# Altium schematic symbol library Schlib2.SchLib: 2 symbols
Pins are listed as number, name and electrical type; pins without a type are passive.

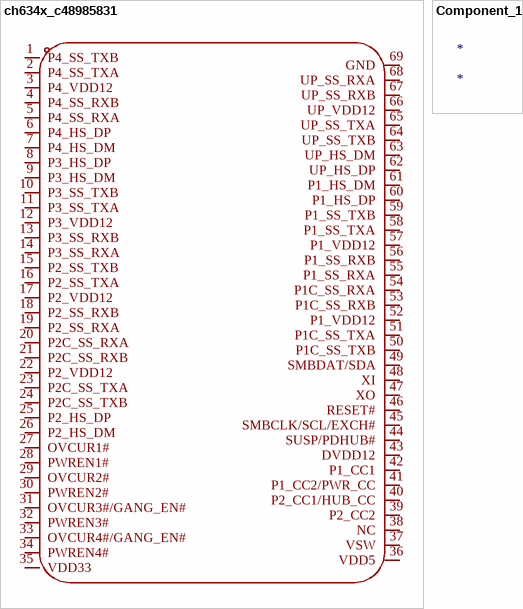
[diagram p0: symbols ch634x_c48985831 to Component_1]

## ch634x_c48985831
designator U??  (value not drawn)
符合USB3.2 Gen1协议规范的4端口USB超高速HUB控制器芯片,CH634X内置两组Type-C双通道USB3.0 PHY和双PD PHY，原生支持Type-C正反插自适应，原生支持PDHUB、Type-C15W和PD100W快充。; Manufacturer: WCH(南京沁恒); ManufacturerPart: CH634X; AddInBom: yes; ModelId: 72236333b5b14e54ba405b685275d4d4; ModelName: QFN-68_L8.0-W8.0-H0.8-P0.40-BL-EP; ModelTransform: 314.96,314.96,0,90,0,0,0,0,0; USB Protocol: USB 3.2; Data Rate: 5Gbps; Voltage - Supply: 3.3V；1.23V; Number of Channels: 4
footprint QFN-68_L8.0-W8.0-P0.40-BL-EP6.2
pins: 1 P4_SS_TXB, 2 P4_SS_TXA, 3 P4_VDD12, 4 P4_SS_RXB, 5 P4_SS_RXA, 6 P4_HS_DP, 7 P4_HS_DM, 8 P3_HS_DP, 9 P3_HS_DM, 10 P3_SS_TXB, 11 P3_SS_TXA, 12 P3_VDD12, 13 P3_SS_RXB, 14 P3_SS_RXA, 15 P2_SS_TXB, 16 P2_SS_TXA, 17 P2_VDD12, 18 P2_SS_RXB, 19 P2_SS_RXA, 20 P2C_SS_RXA, 21 P2C_SS_RXB, 22 P2_VDD12, 23 P2C_SS_TXA, 24 P2C_SS_TXB, 25 P2_HS_DP, 26 P2_HS_DM, 27 OVCUR1#, 28 PWREN1#, 29 OVCUR2#, 30 PWREN2#, 31 OVCUR3#/GANG_EN#, 32 PWREN3#, 33 OVCUR4#/GANG_EN#, 34 PWREN4#, 35 VDD33, 36 VDD5, 37 VSW, 38 NC, 39 P2_CC2, 40 P2_CC1/HUB_CC, 41 P1_CC2/PWR_CC, 42 P1_CC1, 43 DVDD12, 44 SUSP/PDHUB#, 45 SMBCLK/SCL/EXCH#, 46 RESET#, 47 XO, 48 XI, 49 SMBDAT/SDA, 50 P1C_SS_TXB, 51 P1C_SS_TXA, 52 P1_VDD12, 53 P1C_SS_RXB, 54 P1C_SS_RXA, 55 P1_SS_RXA, 56 P1_SS_RXB, 57 P1_VDD12, 58 P1_SS_TXA, 59 P1_SS_TXB, 60 P1_HS_DP, 61 P1_HS_DM, 62 UP_HS_DP, 63 UP_HS_DM, 64 UP_SS_TXB, 65 UP_SS_TXA, 66 UP_VDD12, 67 UP_SS_RXB, 68 UP_SS_RXA, 69 GND

## Component_1
designator *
